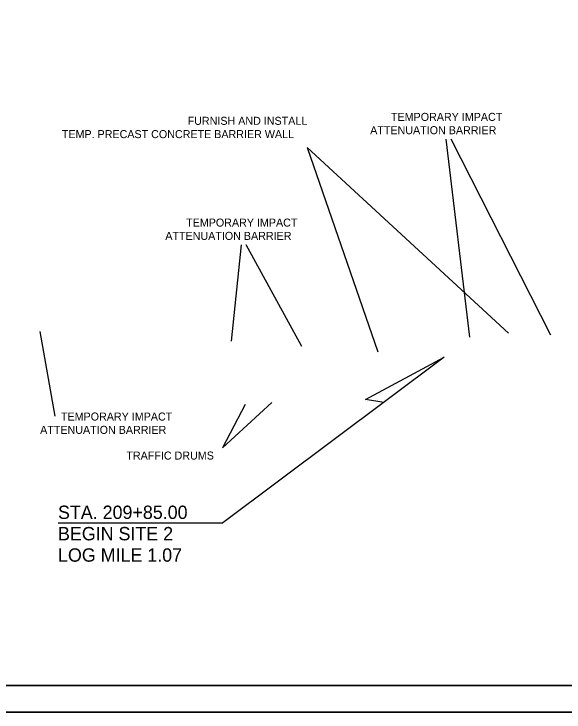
# Model space of a CAD drawing. Extents: x 1398460 to 1408037, y 380768 to 383968.
# Drawn here: x 1401149 to 1401561, y 380768 to 381290 of the extents above; entities that cross this region are included whole.
import ezdxf

# ---------------------------------------------------------------- set-up
doc = ezdxf.new("R2010")
doc.units = 0
for name, color, linetype in [('Default', 7, 'Continuous'), ('MOT STAGE ALL', 7, 'Continuous'), ('R_Border', 7, 'Continuous'), ('R_Dimension', 7, 'Continuous'), ('R_MOT', 7, 'Continuous'), ('R_No Plot', 7, 'Continuous')]:
    doc.layers.add(name, color=color, linetype=linetype)

msp = doc.modelspace()

# ---------------------------------------------------------------- linework, layer by layer
at = {"layer": 'Default'}
for p in [(1401471.62, 381033.31), (1401182.34, 380909.21)]:
    msp.add_line(p, (1401305.83, 380909.21), dxfattribs=at)
msp.add_lwpolyline([(1401426.42, 380999.48), (1401412.64, 381001.6), (1401471.62, 381033.31)], dxfattribs=at)
at = {"layer": 'R_Border'}
msp.add_line((1402308.47, 380787.43), (1400727.57, 380787.43), dxfattribs=at)
at = {"layer": 'R_Dimension'}
msp.add_lwpolyline([(1401322.57, 380997.98), (1401305.43, 380965.31), (1401342.44, 380999.43)], dxfattribs=at)
at = {"layer": 'R_MOT'}
for p, q in [((1401472.92, 381196.65), (1401490.6, 381048.42)), ((1401476.56, 381196.89), (1401551.12, 381049.98)), ((1401368.92, 381190.36), (1401421.77, 381037.33)), ((1401368.92, 381190.36), (1401519.87, 381051.26)), ((1401319.48, 381117.48), (1401312.05, 381045.39)), ((1401323.12, 381117.72), (1401364.82, 381041.52)), ((1401168.65, 381052.44), (1401180.07, 380989.19))]:
    msp.add_line(p, q, dxfattribs=at)
at = {"layer": 'R_No Plot'}
msp.add_line((1400665.56, 380767.54), (1402332.23, 380767.54), dxfattribs=at)
for points in [[(1400665.53, 381834.2), (1402332.23, 381834.2), (1402332.23, 380767.52), (1400665.53, 380767.52)], [(1400727.57, 381814.73), (1400727.57, 380787.43), (1402308.47, 380787.43), (1402308.47, 381643.67), (1402191.82, 381643.67), (1402191.82, 381765.33), (1401995.27, 381765.33), (1401995.27, 381814.73)], [(1401897.17, 381814.73), (1401995.27, 381814.73), (1401995.27, 381765.33), (1402075.83, 381765.33), (1402191.82, 381765.33), (1402191.82, 381643.67), (1402308.47, 381643.67), (1402308.47, 380787.43), (1400727.57, 380787.43), (1400727.57, 381814.73)], [(1400727.57, 380787.43), (1400727.57, 381301.08), (1402308.47, 381301.08), (1402308.47, 380787.43)]]:
    msp.add_lwpolyline(points, close=True, dxfattribs=at)

# ---------------------------------------------------------------- texts
at = {"layer": 'MOT STAGE ALL'}
for s, p in [('FURNISH AND INSTALL', (1401279.43, 381207.37)), ('TEMPORARY IMPACT', (1401431.74, 381210.31)), (' TEMP. PRECAST CONCRETE BARRIER WALL', (1401183, 381197.41)), (' ATTENUATION BARRIER', (1401413.93, 381200.35)), ('TEMPORARY IMPACT', (1401278.3, 381131.14)), (' ATTENUATION BARRIER', (1401260.49, 381121.18)), ('TEMPORARY IMPACT', (1401184.55, 380985.85)), (' ATTENUATION BARRIER', (1401166.74, 380975.89))]:
    msp.add_text(s, height=6.0001, rotation=0, dxfattribs=at).set_placement(p)
at = {"layer": 'R_Border'}
msp.add_text('TRAFFIC DRUMS', height=6, dxfattribs=at).set_placement((1401233.54, 380956.63))
at = {"layer": 'R_Dimension'}
for s, p in [('STA. 209+85.00', (1401182.34, 380912.13)), ('BEGIN SITE 2', (1401182.34, 380896.13)), ('LOG MILE 1.07', (1401182.34, 380880.13))]:
    msp.add_text(s, height=10, dxfattribs=at).set_placement(p)

doc.saveas('drawing.dxf')
